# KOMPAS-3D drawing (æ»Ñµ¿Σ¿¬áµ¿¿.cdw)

Views: Вид 1, Вид 2, Вид 3
Referenced files in C:\Program Files\ASCON\KOMPAS-3D V10\Sys\: GRAPHIC.LHS
Referenced files: 2009-07-06-И-26-КР511.cdw
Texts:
  Текст на чертеже
  Размерные надписи
  Шероховатость
  Линия-выноска #1
  Линия-выноска #2
  Линия-выноска #3
  Отклонения формы и база
  Заголовок таблицы
  Ячейка таблицы
  Стрелка вида
  Обозначение изменения
  Фигурная скобка
  Номер узла
  Марка координационной оси
  VRCB
  Выносная надпись
  Обозначение узла
  Марка/позиционное обозначение с линией-выноской
  Марка/позиционное обозначение на линии
  Марка/позиционное обозначение без линии-выноски
  Материал-Предприятие
  Лит-Масса-Масштаб
  FR4
  Примечания
  Общие указания смотри на листе 1.
  Разрезы 1-1, 2-2, 3-3 смотри ни листе 5.
  Разрезы 4-4, 5-5, 6-6, 7-7 смотри на листе 6.
  Разрезы 8-8, 10-10 смотри на листе 7.
  Разрезы 9-9, 11-11, 12-12, 13-13 смотри на листе 8.
  Вдоль осей "2", "3", "5", "6" между осями "Б", "В" предусмотрены деформационные швы
  с заполнением материалом Пеноплэкс 35.
  Расход материалов на устройство 4-х деформационных швов - пеноплэкс 35 -
  0,4 м 3  при толщине листов 40 мм.
  Разрезы 4-4, 5-5, 6-6, 7-7 замаркированы ни листах 3, 4.
  Под фундаментные плиты, лестничные марши и лестничные площадки выполнить подготовку
  из щебня фракции 20-40 мм толщиной 100 мм с прокладкой между щебнем и бетоном
  монолитных конструкций одного слоя гидроизоляции из гидроизоляционного материала
  Биполь ХПП 3,0.
  Каркасы подпорных стен и сетки лестничных маршей и лестничных площадок выполнить из
  из отдельных стержней из арматуры класса АIII по ГОСТ 5781-82*. Соединения арматуры
  выполнить вязальной проволокой диаметром 1,2-1,5 мм по ГОСТ 3282-74 в шахматном порядке,
  а по краю элементов конструкции лестницы-спуска в каждом пересечении .
  Арматурные стержни по длине соединяются в холодный стык с нахлёстом величиной в 40
  диаметров соединяемых стержней, или при помощи ручной дуговой сварки (тип соединения
  С23-Рэ по ГОСТ 14098-91) с длиной шва 8 диаметров соединяемых стержней.
  Нижняя арматура укладывается на фиксаторы защитного слоя толщиной 40 мм. Защитный
  слой вертикальной арматуры подпорных стен - 40 мм.
  Поз.
  Марка.
  Кол-во
  ед, кг
  ПЛм-1
  ПС-3а
  ЛМ-1а
  ЛМ-1б
  ПС-2
  ПС-1
  Щебень фр. 20-40 мм
  Площадка лестничная монолитная ПЛм-1
  Материалы
  Бетон класса В20 W6 F300
  Биполь ХПП 3,0
  Подпорная стена ПС-3а
  Лестничный марш ЛМ-1а
  Лестничный марш ЛМ-1б
  Подпорная стена ПС-2
  Подпорная стена ПС-1
  ПС-3б
  ЛМ-2
  ПЛм-2
  Подпорная стена ПС-3б
  Лестничный марш ЛМ-2
  Площадка лестничная монолитная ПЛм-2
  ЛМ-3
  ПС-5
  ПС-4б
  ПС-4а
  Лестничный марш ЛМ-3
  Подпорная стена ПС-5
  Подпорная стена ПС-4б
  Подпорная стена ПС-4а
  ПС-6
  ПС-7
  ПЛм-3
  ПС-8
  ЛМ-4
  Подпорная стена ПС-6
  Подпорная стена ПС-7
  Площадка лестничная монолитная ПЛм-3
  Подпорная стена ПС-8
  Лестничный марш ЛМ-4
  ПС-9б
  ПЛм-4
  ПС-9а
  Подпорная стена ПС-9б
  Площадка лестничная монолитная ПЛм-4
  Подпорная стена ПС-9а
  ПС-10а
  ПС-10б
  ЛМ-5
  ПЛм-5
  ПС-13
  Подпорная стена ПС-10а
  Подпорная стена ПС-10б
  Лестничный марш ЛМ-5
  Площадка лестничная монолитная ПЛм-5
  Подпорная стена ПС-13
  ПС-12
  ПС-11б
  ПС-11а
  Подпорная стена ПС-12
  Подпорная стена ПС-11б
  Подпорная стена ПС-11а
  ПС-14
  ПС-15
  ПС-16а
  ПС-16б
  Подпорная стена ПС-15
  Подпорная стена ПС-16а
  Подпорная стена ПС-16б
  ЛМ-6
  ПЛм-6
  Лестничный марш ЛМ-6
  Площадка лестничная монолитная ПЛм-6
  ЛМ-7
  ПЛм-7
  Лестничный марш ЛМ-7
  Площадка лестничная монолитная ПЛм-7
  Спецификация на 1 элемент
  Ведомость расхода стали на элемент, кг
  Марка
  элемента
  Изделия арматурные
  Арматура класса, кг
  Всего:
  АIII
  ГОСТ 5781-82*
  Итого:
  Монолитная лестничная площадка ПЛм-1
  Монолитная лестничная площадка ПЛм-2
  Монолитная лестничная площадка ПЛм-3
  Монолитная лестничная площадка ПЛм-4
  Монолитная лестничная площадка ПЛм-5
  Монолитная лестничная площадка ПЛм-6
  Подпорная стена ПС-14
  Монолитная лестничная площадка ПЛм-7
  Спецификация к схеме расположения монолитных
  железобетонных конструкций.
  CONTINUOUS_RGB_0_0_0_THICK_0.3
  CONTINUOUS_RGB_0_0_0_THICK_0.18
  POLYLINE_STYLE_0.18_RGB_0_0_0
  CONTINUOUS_RGB_0_0_0_THICK_0.35
  CONTINUOUS_RGB_0_0_0_THICK_0.2
  CONTINUOUS_RGB_0_255_255_THICK_0.25
  CONTINUOUS_RGB_0_255_255_THICK_0.4
  CONTINUOUS_RGB_0_0_0_THICK_0.4
  CONTINUOUS_RGB_0_0_0_THICK_0.13
  CONTINUOUS_RGB_255_0_0_THICK_0.35
  CONTINUOUS_RGB_0_255_255_THICK_0.35
  CONTINUOUS_RGB_0_255_255_THICK_0.13
  GOST2.303 6_RGB_0_0_0_SC_0.1_THICK_0
  CONTINUOUS_RGB_255_255_0_THICK_0.25
  CONTINUOUS_RGB_0_255_255_THICK_0.3
  CONTINUOUS_RGB_0_0_0_THICK_0.25
  CONTINUOUS_RGB_255_255_0_THICK_0.3
  CONTINUOUS_RGB_255_255_0_THICK_0.35
  СТИЛИ-ЛИНИЙ-ПУНКТИРНАЯ-ЛИНИЯ_RGB_255_255_0_SC_0.08_THICK_0
  CONTINUOUS_RGB_255_0_0_THICK_0.25
  POLYLINE_STYLE_0.18_RGB_255_255_0
  CONTINUOUS_RGB_255_255_0_THICK_0.4
  POLYLINE_STYLE_0.18_RGB_255_0_0
  CONTINUOUS_RGB_0_0_0_THICK_0.09
  CONTINUOUS_RGB_192_192_192_THICK_0.13
  CONTINUOUS_RGB_0_0_0_THICK_0.15
  Штрихштриховая_RGB_0_0_0_SC_1_THICK_0.18
  С изломами_RGB_0_0_0_SC_1_THICK_0.18
  style from library
  Монтажный
  Заводской
  СПЛОШНАЯ_И_ШТРИХПУНКТИРНАЯ_ANSI
  СПЛОШНАЯ_И_ШТРИХПУНКТИРНАЯ_ANSI 1
  ГРУНТ_ANSI
  ГРУНТ_ANSI 3
  AR-CONC_ANSI
  AR-CONC_ANSI 12
  AR-CONC_ANSI 11
  AR-CONC_ANSI 10
  AR-CONC_ANSI 9
  AR-CONC_ANSI 8
  AR-CONC_ANSI 7
  AR-CONC_ANSI 6
  AR-CONC_ANSI 5
  AR-CONC_ANSI 4
  AR-CONC_ANSI 3
  AR-CONC_ANSI 2
  AR-CONC_ANSI 1
  AR-CONC_ANSI 0
  Стили документа
  Реконструкция существующей лестницы-
  спуска с Комсомольского проспекта
  ЗАО Институт "ПИРС"
  Схема расположения монолитных
  Разраб.
  Пелянёв
Dimensions and other numbers on the sheet: 2009/07-06-И-26-КР; 1; 7; 3,7; 7,0; 34,7; 3,5; 2; 30,4; 37,2; 86,4; 8,6; 5,7; 27,0; 2,7; 5,5; 25,8; 2,6; 64,2; 0,617; 1,58; 2,47; 235,5 кг; 615,6 кг; 183,3 кг; 175,1 кг; 1643,0 кг; 3493,4 кг; 1667,3 кг; 1439,5 кг; 13,0; 14,3; 1,4; 7,5; 15,6; 73,2; 7,3; 3,9; 19,5; 2,0; 353,6 кг; 496,8 кг; 132,3кг; 1,1; 17,8; 1,8; 4,7; 11,0; 10,1; 120,8 кг; 368,0 кг; 477,7 кг; 218,0 кг; 7,2; 6,2; 0,6; 7,4; 9,2; 0,9; 17,5; 6,8; 0,8; 6,1; 9,0; 4,0; 17,9; 347,7 кг; 118,8 кг; 322,7 кг; 365,6 кг; 156,8 кг; 121,5 кг; 1,3; 12,8; 1,9; 18,6; 210,5 кг; 521,4 кг; 126,2 кг; 4,5; 10,0; 1,0; 14,2; 14,7; 1,5; 7,7; 16,4; 76,2; 7,6; 3,6; 17,6; 62,1; 71,1; 7,1; 3,85; 671,5 кг; 359,0 кг; 517,2 кг; 119,5 кг; 2264,2 кг; 2386,0 кг; 1582,0 кг; 5,1; 11,9; 1,2; 10,2; 76,2 кг; 411,3 кг; 483,0 кг; 237,9 кг; 8,7; 8,9; 5,8; 0,5; 9,1; 14,6; 16,9; 1,7; 5,6; 11,7; 276,5 кг; 428,5 кг; 692,1 кг; 262,2 кг; 4,1; 18,3; 20,2; 124,2 кг; 137,1 кг; 4,9; 24,3; 2,4; 164,9 кг; 1643,0; 1439,5; 183,3; 175,1; 235,5; 615,6; 353,6; 496,8; 132,3; 477,7; 218,0; 368,0; 347,7; 120,8; 118,8; 322,7; 156,8; 521,4; 210,5; 3493,4; 365,6; 1667,3; 6803,7; 522,4; 121,5; 126,2; 671,5; 359,0; 517,2; 119,5; 483,0; 237,9; 411,3; 1582,0; 124,2; 137,1; 276,5; 428,5; 262,2; 164,9; 2386,0; 2264,2; 487,5; 6232,2; 2009/07-06-И-26-КР-5; 2009/07-06-И-26-КР-6; 2009/07-06-И-26-КР-7; 2009/07-06-И-26-КР-8; 2009/07-06-И-26-КР-; 3; 03.11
